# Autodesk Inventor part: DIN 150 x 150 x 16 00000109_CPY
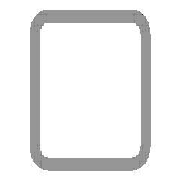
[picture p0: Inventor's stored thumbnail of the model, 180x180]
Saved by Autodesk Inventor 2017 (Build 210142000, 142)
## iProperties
Created: 2017-11
Part Number: DIN 150 x 150 x 16 00000109_CPY
Material: Steel, Mild
Description: Cold formed welded structural hollow sections of non-alloy and fine grain structural steel
Document SubType Name: Modeling
Standard: DIN
Designer: iusti
Standard Revision: 2006-07
Standards Organization: DIN
Language: en-US
Size Designation: 150 x 150 x 16
Categories: <MemberInstance><Categories><Category DisplayName="Structural Shapes" InternalName="089c4875-fa83-4c05-b084-43b9cc11f5ed" Mnemonic="GRDR"><CategoryParameter Dis
Stock Number: 150 x 150 x 16
Mass: 49891.9 g
Surface Area: 8094.11 cm^2
Volume: 6355.65 cm^3
Density: 7.85 g/cm^3
Appearance: Semi-Polished
IsCustomPart: 1
G_W: 150.000 mm
G_H: 150.000 mm
G_L: 850.000 mm
+3725B7E9-7AF2-4E59-89A6-3A300E17AA57+CUTDETAIL3: Cut
+D51DAF0C-9B75-4607-A0B5-4213B0D9FE2B+CUTDETAIL4: Cut
_CCFamilyMember: 76
_CCFamilyDisplayName: DIN EN 10219-2 (Square Hollow Section - Cold Formed) - Cold formed welded structural hollow sections of non-alloy and fine grain structural steel
_FrameMemberDoc: Frame Member File
_Version: 15.0.0
_GetPNFromCC: 1
Author: iusti
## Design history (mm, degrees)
node "Start plane"
node "End plane"
sketch "Sketch"
  geometry: L1 (-75, -27)-(-75, 27); L2 (-27, 75)-(27, 75); L3 (75, 27)-(75, -27); L4 (27, -75)-(-27, -75); L5 (-27, 59)-(27, 59); L6 (59, 27)-(59, -27); L7 (27, -59)-(-27, -59); L8 (-59, -27)-(-59, 27); L9 (0, 118.918)-(0, -118.918) reference; L10 (-118.918, 0)-(118.918, 0) reference; A1 r 48 centre (-27, -27) between (-75, -27) and (-27, -75); A2 r 48 centre (-27, 27) between (-27, 75) and (-75, 27); A3 r 48 centre (27, 27) between (75, 27) and (27, 75); A4 r 48 centre (27, -27) between (27, -75) and (75, -27); A5 r 32 centre (-27, 27) between (-27, 59) and (-59, 27); A6 r 32 centre (27, 27) between (59, 27) and (27, 59); A7 r 32 centre (27, -27) between (27, -59) and (59, -27); A8 r 32 centre (-27, -27) between (-59, -27) and (-27, -59)
  constraints: 16 end point, 16 point on circle, 8 centre point, 8 tangent, 4 parallel, 3 equal radius, 2 perpendicular, 7 other
  dimensions: "d7" = 48 radius of A1 (= G_IR); "d10" = 150 distance between parallel lines of L2 L4 (= G_H); "d11" = 150 distance between parallel lines of L1 L3 (= G_W); "d12" = 16 distance between parallel lines of L3 L6 (= G_T); "d15" = 75 distance between parallel lines of L2 L10 (= 0.5 x d10); "d16" = 75 distance between parallel lines of L9 L3 (= 0.5 x d11)
extrude "Body" new body sketch "Sketch" stored distance "d3" = 850 (= G_L); taper "d4" = 0 deg
node "Driven Length"
  sketch "Sketch3"
    geometry: L1 (0, 0)-(10, 0) reference
    constraints: 2 end point, 1 horizontal
  workplane "Work Plane3"
  sketch "Sketch4"
    geometry: L1 (-2, 75)-(12, 75) reference; L2 (-2, 925)-(12, 925) reference
    dimensions: "d18" = 850 distance between parallel lines of L1 L2 (derived)
workplane "Work Plane4"
split "Split1"
workplane "Work Plane5"
split "Split2"
body "Solid1"
other parameters: "G_W" = 150 [user parameter; used in 1 equation term], "G_H" = 150 [user parameter; used in 1 equation term], "G_T" = 16 [user parameter; used in 1 equation term], "G_IR" = 48 [user parameter; used in 1 equation term], "G_L" = 850 (= d18) [user parameter; used in 1 equation term], "G_OFFSET_START" = -75 [user parameter; used in 1 equation term], "G_OFFSET_END" = -110.90437 [user parameter; used in 1 equation term], "d13" = 75 (= -G_OFFSET_START), "d14" = 925 (= G_OFFSET_END + B_L), "B_L" = 1035.90437 [user parameter; used in 1 equation term], "d17" = 90 deg
